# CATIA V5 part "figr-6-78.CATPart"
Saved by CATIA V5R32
Part number: Part1
Bounding box of the stored display mesh (mm): x -73.764 to 84.089, y -55.398 to 52.667, z 0 to 40
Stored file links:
  D:\PROJECTS\Project 2022\CATIA V5 6R 2022\Resources\Part Files\c06_catia_v5_6r2022_prt\figr-6-78.CATPart
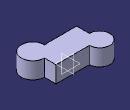
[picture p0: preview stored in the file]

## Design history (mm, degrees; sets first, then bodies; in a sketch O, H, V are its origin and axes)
Body1 (main body)
  Sketch1 on xy-plane, origin (0, 0, 0), H (1, 0, 0), V (0, 1, 0)
    arc A1 centre (-49.155, 28.0584) radius 24.6929 from (-24.4621, 28.0584) to (-49.155, 3.3655) ccw
    line L1 (-24.4621, 28.0584) -> (56.3278, 28.0584)
    line L2 (56.3278, 28.0584) -> (56.3278, 0.211)
    line L3 (28.4803, -27.6365) -> (-49.155, -27.6365)
    line L4 (-49.155, -27.6365) -> (-49.155, 3.3655)
    arc A2 centre (56.3278, -27.6365) radius 27.8474 from (28.4803, -27.6365) to (56.3278, 0.211) ccw
    point P5 (56.3278, 0.211)
    horizontal: L1 H, L3 H
    vertical: L2 V, L4 V
    coincidence: A2 P5, L2 P5
  Pad1: profile Sketch1, direction (0, 0, 1), length 30
  Thickness1: Face end face of Pad1, Thickness 10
